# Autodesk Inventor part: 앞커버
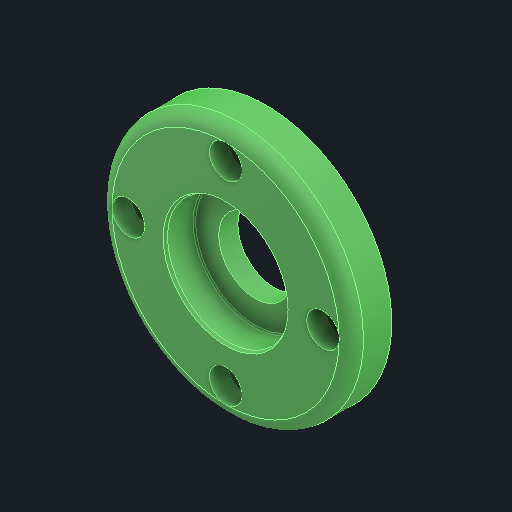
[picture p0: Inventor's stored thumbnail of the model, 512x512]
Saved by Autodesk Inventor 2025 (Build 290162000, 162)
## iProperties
Created: 2025-08
Part Number: 앞커버
Material: 알루미늄 6061
Document SubType Name: Modeling
Designer: infra15
Density: 2.71 g/cm^3
Appearance: 기본값
Sending System: Autodesk Inventor 2026
Preprocessor: ST-DEVELOPER v20.1
Author: jhkim
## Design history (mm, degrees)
feature "솔리드1"
node "솔리드2"
